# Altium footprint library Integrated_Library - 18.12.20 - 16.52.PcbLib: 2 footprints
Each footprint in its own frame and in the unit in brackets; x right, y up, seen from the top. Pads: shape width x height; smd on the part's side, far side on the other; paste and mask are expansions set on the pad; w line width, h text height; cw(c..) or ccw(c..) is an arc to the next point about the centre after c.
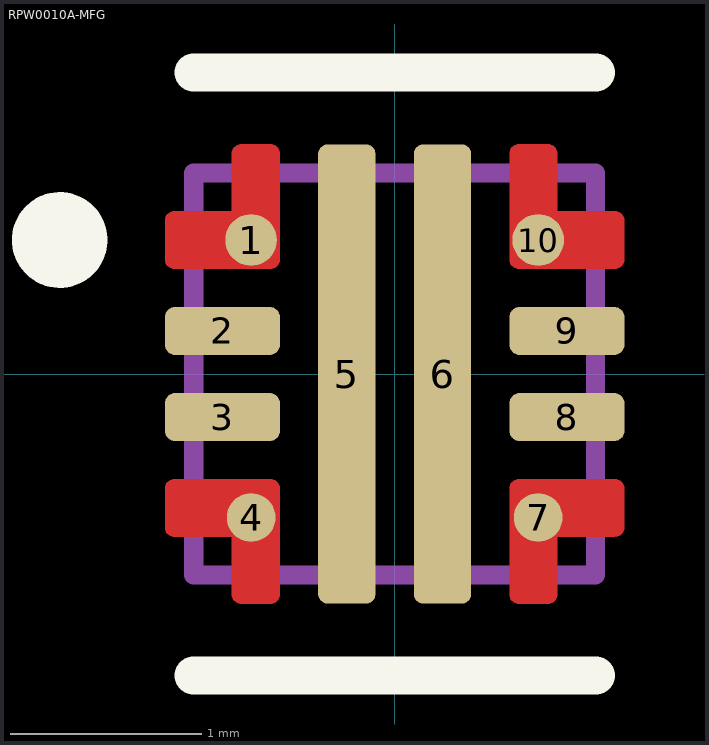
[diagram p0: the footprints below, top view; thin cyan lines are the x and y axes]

## PCBComponent_1 [mm]

## RPW0010A-MFG [mm]
pads (10):
  round 0.27 smd paste-1000 mask+0: 1(-0.75,0.7) 10(0.75,0.7)
  rrect40% 0.6x0.25 smd paste+0 mask+0: 2(-0.9,0.225) 3(-0.9,-0.225) 8(0.9,-0.225) 9(0.9,0.225)
  round 0.255 smd paste-1000 mask+0: 4(-0.75,-0.75) 7(0.75,-0.75)
  rrect33% 0.3x2.4 smd paste-1000 mask+0: 5(-0.25,0) 6(0.25,0)
Top Layer:
  region: -0.85,0.85 -0.85,1.15 -0.85,1.16 -0.842,1.178 -0.828,1.192 -0.81,1.2 -0.8,1.2 -0.65,1.2 -0.64,1.2 -0.622,1.192 -0.608,1.178 -0.6,1.16 -0.6,1.15 -0.6,0.6 -0.6,0.59 -0.608,0.572 -0.622,0.558 -0.64,0.55 -0.65,0.55 -1.15,0.55 -1.16,0.55 -1.178,0.558 -1.192,0.572 -1.2,0.59 -1.2,0.6 -1.2,0.8 -1.2,0.81 -1.192,0.828 -1.178,0.842 -1.16,0.85 -1.15,0.85
  region: -0.85,-0.85 -0.85,-1.15 -0.85,-1.16 -0.842,-1.178 -0.828,-1.192 -0.81,-1.2 -0.8,-1.2 -0.65,-1.2 -0.64,-1.2 -0.622,-1.192 -0.608,-1.178 -0.6,-1.16 -0.6,-1.15 -0.6,-0.6 -0.6,-0.59 -0.608,-0.572 -0.622,-0.558 -0.64,-0.55 -0.65,-0.55 -1.15,-0.55 -1.16,-0.55 -1.178,-0.558 -1.192,-0.572 -1.2,-0.59 -1.2,-0.6 -1.2,-0.8 -1.2,-0.81 -1.192,-0.828 -1.178,-0.842 -1.16,-0.85 -1.15,-0.85
  region: 0.85,-0.85 0.85,-1.15 0.85,-1.16 0.842,-1.178 0.828,-1.192 0.81,-1.2 0.8,-1.2 0.65,-1.2 0.64,-1.2 0.622,-1.192 0.608,-1.178 0.6,-1.16 0.6,-1.15 0.6,-0.6 0.6,-0.59 0.608,-0.572 0.622,-0.558 0.64,-0.55 0.65,-0.55 1.15,-0.55 1.16,-0.55 1.178,-0.558 1.192,-0.572 1.2,-0.59 1.2,-0.6 1.2,-0.8 1.2,-0.81 1.192,-0.828 1.178,-0.842 1.16,-0.85 1.15,-0.85
  region: 0.85,0.85 0.85,1.15 0.85,1.16 0.842,1.178 0.828,1.192 0.81,1.2 0.8,1.2 0.65,1.2 0.64,1.2 0.622,1.192 0.608,1.178 0.6,1.16 0.6,1.15 0.6,0.6 0.6,0.59 0.608,0.572 0.622,0.558 0.64,0.55 0.65,0.55 1.15,0.55 1.16,0.55 1.178,0.558 1.192,0.572 1.2,0.59 1.2,0.6 1.2,0.8 1.2,0.81 1.192,0.828 1.178,0.842 1.16,0.85 1.15,0.85
Top Overlay:
  circle w0.25: c-1.75,0.7 r0.125
  lines w0.2: -1.05,-1.575 1.05,-1.575 ; -1.05,1.575 1.05,1.575
Top Paste:
  drawing of 8 lines, arcs and shapes, not listed
Mechanical 5:
  lines w0.1: -1.05,-1.05 1.05,-1.05 1.05,1.05 -1.05,1.05 -1.05,-1.05
  text ".Designator" at 0,0 h0.5
3D body "IC_TPS259470ARPWT_QFN10.STEP": height 0.25, standoff 0, extent -1.3,-1.3 1.3,1.3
